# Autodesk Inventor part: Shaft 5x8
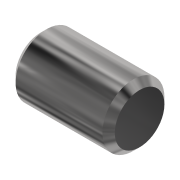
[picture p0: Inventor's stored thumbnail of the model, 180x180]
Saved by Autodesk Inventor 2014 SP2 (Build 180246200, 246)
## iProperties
Created: 2016-02
Part Number: Shaft 5x8
Material: Steel
Document SubType Name: Modeling
Designer: User
Density: 7.85 g/cm^3
Appearance: Steel - Polished
Author: User
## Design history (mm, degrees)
sketch "Sketch1"
  geometry: L1 (-4, 2.5)-(4, 2.5); L2 (4, 2.5)-(4, 0); L3 (4, 0)-(-4, 0); L4 (-4, 0)-(-4, 2.5); 2 further points
  constraints: 8 end point, 2 parallel, 1 coincident, 1 horizontal, 1 midpoint, 1 perpendicular
  dimensions: "d0" = 5 diameter of L1 L3; "d1" = 8 distance of L1.start L1.end
revolve "Revolution1" sketch "Sketch1" stored, may be unused: angle "d2" = 90 deg
chamfer "Chamfer1" distance "d3" = 0.5; stored, may be unused: second distance "d4" = 2, angle "d5" = 45 deg
body "Solid1"
